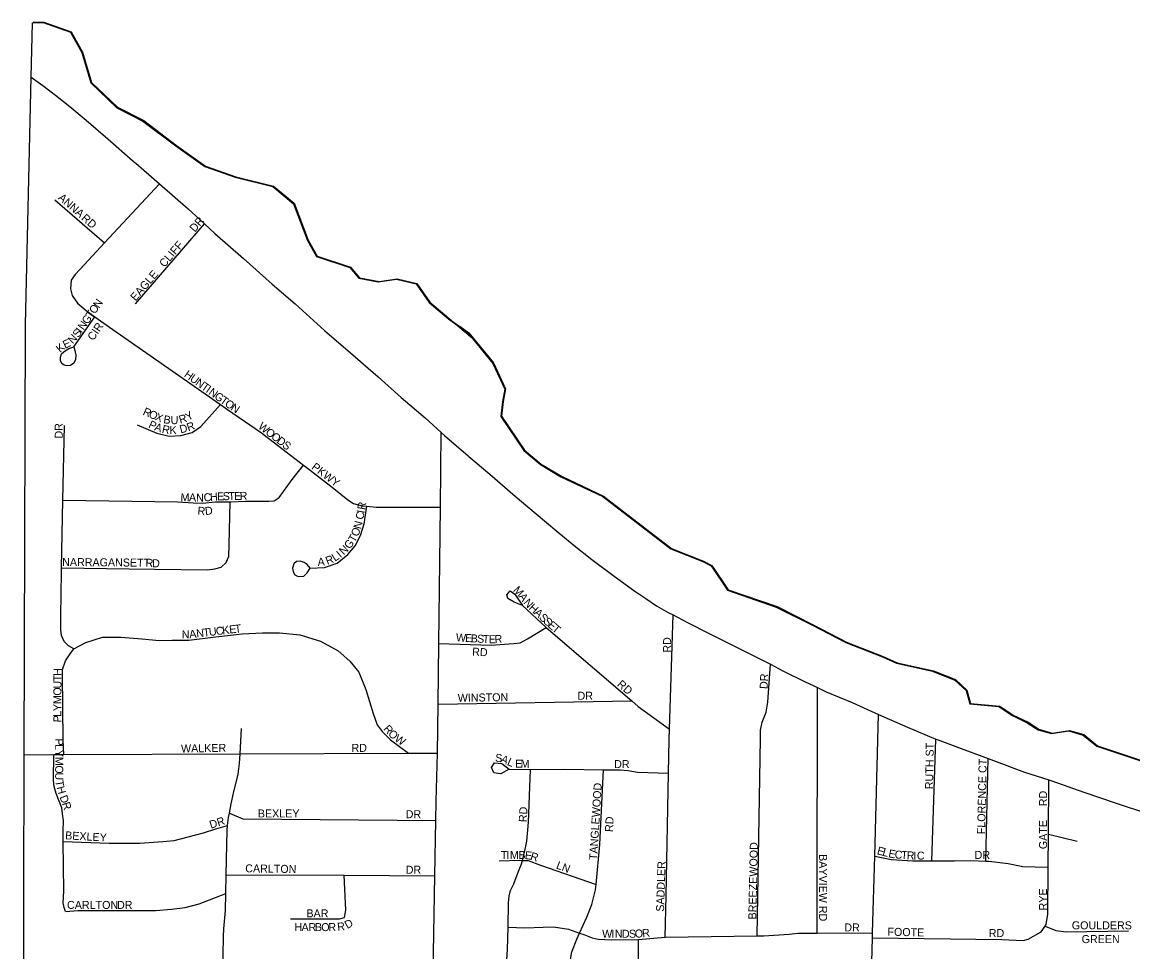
# Model space of a CAD drawing. Extents: x -561 to 1170, y 0 to 846.
# Drawn here: x 38.1 to 56.84, y 277.44 to 293.13 of the extents above; entities that cross this region are included whole.
import ezdxf

# ---------------------------------------------------------------- set-up
doc = ezdxf.new("R2010")
doc.units = 0
for name, color, linetype in [('GM_X_City_Street', 7, 'Continuous'), ('GM_X_City_Street_Text', 7, 'Continuous'), ('GM_X_County', 7, 'Continuous'), ('GM_X_Major_Lake', 7, 'Continuous'), ('GM_X_Major_River', 7, 'Continuous'), ('GM_X_US_Route', 7, 'Continuous')]:
    doc.layers.add(name, color=color, linetype=linetype)

msp = doc.modelspace()

# ---------------------------------------------------------------- linework, layer by layer
at = {"layer": 'GM_X_City_Street'}
for points in [[(40.416, 290.402), (39.489, 289.406), (39.15, 289.041), (38.994, 288.867), (38.929, 288.775), (38.913, 288.629), (38.946, 288.515), (39.033, 288.385), (39.18, 288.261), (39.328, 288.157), (39.63, 287.944), (41.446, 286.674), (41.562, 286.593), (42.138, 286.2), (42.556, 285.876), (42.849, 285.652), (42.958, 285.569), (43.359, 285.257), (43.593, 285.068), (43.69, 285.009), (43.837, 284.967), (43.914, 284.96), (44.07, 284.946), (44.441, 284.946), (44.441, 284.946)], [(38.653, 290.128), (39.489, 289.406)], [(40.013, 288.373), (41.174, 289.726)], [(38.971, 287.648), (38.99, 287.586), (39.005, 287.511), (39, 287.433), (38.971, 287.372), (38.918, 287.337), (38.853, 287.328), (38.808, 287.34), (38.767, 287.366), (38.745, 287.419), (38.744, 287.474), (38.762, 287.53), (38.809, 287.572), (38.885, 287.622), (38.971, 287.648), (39.328, 288.157)], [(40.042, 286.331), (40.373, 286.192), (40.579, 286.144), (40.779, 286.156), (40.969, 286.205), (41.114, 286.303), (41.446, 286.674)], [(38.753, 283.185), (38.753, 283.191), (38.755, 283.406), (38.765, 283.921), (38.788, 285.064), (38.814, 286.32)], [(44.832, 266.279), (44.833, 266.436), (44.841, 266.766), (44.894, 269.05), (44.906, 269.574), (44.922, 270.523), (44.94, 271.551), (44.973, 273.529), (45.065, 278.726), (45.081, 279.658), (45.087, 279.984), (45.108, 280.796), (45.117, 281.619), (45.129, 282.643), (45.156, 284.945), (45.17, 286.202)], [(41.977, 285.045), (41.981, 285.045), (42.11, 285.046), (42.261, 285.046), (42.353, 285.052), (42.434, 285.107), (42.655, 285.411), (42.849, 285.652)], [(38.788, 285.064), (40.724, 285.034), (40.984, 285.019), (41.146, 285.014), (41.357, 285.037), (41.607, 285.033), (41.628, 285.033), (41.866, 285.045), (41.977, 285.045)], [(40.332, 283.9), (41.226, 283.888), (41.351, 283.905), (41.459, 283.932), (41.54, 284.009), (41.588, 284.112), (41.593, 284.312), (41.607, 285.033)], [(42.958, 283.917), (42.908, 283.975), (42.855, 284.014), (42.788, 284.034), (42.731, 284.027), (42.683, 283.988), (42.661, 283.916), (42.672, 283.854), (42.702, 283.804), (42.755, 283.776), (42.85, 283.781), (42.91, 283.835), (42.958, 283.917), (43.202, 283.929), (43.413, 284.001), (43.596, 284.148), (43.72, 284.294), (43.806, 284.468), (43.87, 284.663), (43.914, 284.96)], [(44.441, 284.946), (45.156, 284.945)], [(38.765, 283.921), (39.903, 283.905), (39.904, 283.905)], [(39.904, 283.905), (40.33, 283.9), (40.332, 283.9)], [(46.541, 283.286), (46.401, 283.341), (46.293, 283.406), (46.277, 283.466), (46.332, 283.536), (46.413, 283.476), (46.541, 283.286), (46.939, 282.916), (48.387, 281.677), (48.496, 281.584), (49.023, 281.202)], [(38.803, 280.771), (38.791, 281.017), (38.781, 282.117), (38.781, 282.209), (38.829, 282.355), (38.91, 282.469), (38.974, 282.556), (38.882, 282.605), (38.811, 282.68), (38.762, 282.777), (38.751, 282.875), (38.753, 283.185)], [(48.963, 278.387), (48.963, 278.387), (49.006, 280.456), (49.018, 281.024), (49.023, 281.202), (49.082, 283.126)], [(38.974, 282.556), (39.174, 282.66), (39.455, 282.753), (39.769, 282.749), (40.121, 282.724), (40.419, 282.698), (40.63, 282.699), (40.912, 282.7), (41.366, 282.756), (41.81, 282.807), (42.153, 282.823), (42.443, 282.826), (42.784, 282.79), (43.131, 282.683), (43.429, 282.522), (43.63, 282.344), (43.782, 282.16), (43.897, 281.868), (44.023, 281.463), (44.089, 281.273), (44.176, 281.16), (44.312, 281.02), (44.616, 280.794)], [(45.129, 282.643), (46.014, 282.617), (46.236, 282.632), (46.398, 282.643), (46.501, 282.658), (46.625, 282.723), (46.939, 282.916)], [(50.5, 277.714), (50.558, 281.034), (50.559, 281.18), (50.586, 281.315), (50.652, 281.488), (50.68, 281.656), (50.724, 282.295)], [(51.516, 278.185), (51.518, 281.901)], [(45.117, 281.619), (48.387, 281.677)], [(52.182, 266.15), (52.18, 266.4), (52.256, 269.459), (52.259, 269.546), (52.259, 269.555), (52.28, 270.669), (52.296, 271.478), (52.337, 273.526), (52.366, 274.649), (52.392, 275.624), (52.447, 277.681), (52.449, 277.762), (52.484, 279.056), (52.547, 281.447)], [(41.778, 280.782), (41.778, 280.782), (41.8, 281.209)], [(53.446, 278.976), (53.517, 281.033)], [(38.136, 280.768), (38.635, 280.77), (38.803, 280.771), (41.778, 280.782), (44.616, 280.794), (45.108, 280.796)], [(38.829, 278.124), (38.807, 278.189), (38.79, 278.271), (38.801, 278.466), (38.793, 279.305), (38.791, 279.479), (38.796, 279.657), (38.779, 279.771), (38.768, 279.874), (38.724, 279.987), (38.675, 280.112), (38.642, 280.231), (38.626, 280.339), (38.635, 280.77)], [(41.485, 277.074), (41.499, 277.703), (41.504, 277.833), (41.53, 278.142), (41.536, 278.429), (41.542, 278.744), (41.553, 279.247), (41.557, 279.491), (41.567, 279.576), (41.583, 279.708), (41.597, 279.783), (41.626, 279.941), (41.668, 280.12), (41.743, 280.44), (41.769, 280.618), (41.778, 280.782)], [(54.359, 278.974), (54.401, 280.705)], [(46.318, 280.526), (46.175, 280.446), (46.056, 280.465), (46.021, 280.553), (46.07, 280.63), (46.192, 280.621), (46.318, 280.526), (46.675, 280.52), (47.253, 280.523), (47.907, 280.515), (47.983, 280.514), (48.188, 280.513), (48.323, 280.502), (48.48, 280.474), (49.006, 280.456)], [(46.236, 275.563), (46.226, 275.639), (46.236, 276.808), (46.237, 276.981), (46.276, 277.311), (46.288, 277.484), (46.297, 277.858), (46.308, 278.269), (46.314, 278.383), (46.341, 278.48), (46.396, 278.588), (46.467, 278.788), (46.521, 278.913), (46.541, 278.986), (46.576, 279.118), (46.615, 279.313), (46.644, 279.632), (46.675, 280.52)], [(47.346, 277.28), (47.374, 277.442), (47.456, 277.658), (47.503, 277.76), (47.625, 278.026), (47.713, 278.242), (47.774, 278.491), (47.782, 278.577), (47.847, 279.253), (47.907, 280.515)], [(54.991, 277.633), (55.072, 277.659), (55.295, 277.783), (55.359, 277.876), (55.376, 277.902), (55.404, 278.08), (55.41, 278.87), (55.414, 279.428), (55.421, 280.343)], [(41.597, 279.783), (41.822, 279.687), (45.081, 279.658)], [(38.793, 279.305), (39.566, 279.276), (40.086, 279.278), (40.475, 279.307), (40.665, 279.324), (40.903, 279.385), (41.162, 279.451), (41.368, 279.517), (41.567, 279.576)], [(55.414, 279.428), (55.902, 279.312)], [(52.484, 279.056), (52.77, 279), (53.127, 278.977), (53.446, 278.976), (53.522, 278.976), (53.83, 278.98), (54.106, 278.984), (54.359, 278.974), (54.408, 278.972), (54.738, 278.933), (54.957, 278.886)], [(46.149, 278.979), (46.489, 278.988), (46.541, 278.986), (46.635, 278.982), (46.846, 278.906), (47.782, 278.577)], [(54.957, 278.886), (54.97, 278.883), (55.41, 278.87)], [(41.542, 278.744), (43.53, 278.734), (45.065, 278.726)], [(42.629, 278), (43.327, 277.998), (43.452, 277.999), (43.538, 278.021), (43.56, 278.145), (43.53, 278.734)], [(38.829, 278.124), (39.045, 278.142), (39.197, 278.142), (40.063, 278.141), (40.355, 278.142), (40.62, 278.165), (40.848, 278.193), (41.086, 278.254), (41.361, 278.358), (41.536, 278.429)], [(48.948, 277.69), (48.963, 278.387)], [(51.516, 277.757), (51.516, 278.185), (51.516, 278.185)], [(46.297, 277.858), (46.581, 277.851), (46.89, 277.861), (47.063, 277.865), (47.317, 277.827), (47.503, 277.76), (47.576, 277.733), (47.716, 277.679), (47.818, 277.657), (48.045, 277.645), (48.5, 277.654), (48.948, 277.69), (50.5, 277.714), (50.613, 277.716), (51.04, 277.741), (51.186, 277.757), (51.354, 277.756), (51.516, 277.757), (52.449, 277.762)], [(55.359, 277.876), (55.543, 277.803), (55.716, 277.781), (56.765, 277.798)], [(48.479, 275.624), (48.494, 276.674), (48.495, 276.755), (48.5, 277.654)], [(52.447, 277.681), (54.629, 277.65), (54.991, 277.633)]]:
    msp.add_lwpolyline(points, dxfattribs=at)
at = {"layer": 'GM_X_County'}
msp.add_lwpolyline([(38.1, 266.459), (38.136, 280.768), (38.154, 288.024), (38.254, 292.2), (38.276, 293.118), (38.454, 293.119), (38.916, 292.959), (39.107, 292.613), (39.257, 292.104), (39.698, 291.684), (40.138, 291.459), (40.693, 291.039), (41.183, 290.69), (41.693, 290.509), (42.328, 290.355), (42.677, 290.064), (42.913, 289.442), (43.066, 289.172), (43.631, 288.986), (43.778, 288.808), (44.109, 288.745), (44.418, 288.79), (44.749, 288.71), (44.967, 288.397), (45.294, 288.123), (45.623, 287.878), (46.043, 287.371), (46.245, 286.933), (46.203, 286.721), (46.177, 286.472), (46.564, 285.899), (46.847, 285.662), (47.189, 285.458), (47.895, 285.126), (49.043, 284.243), (49.585, 284.029), (49.727, 283.953), (49.999, 283.543), (50.824, 283.26), (51.432, 282.954), (51.997, 282.659), (52.616, 282.418), (52.85, 282.311), (53.462, 282.178), (53.837, 282.028), (54.027, 281.85), (54.088, 281.629), (54.581, 281.582), (54.81, 281.432), (55.059, 281.308), (55.244, 281.19), (55.467, 281.126), (55.759, 281.171), (56.003, 281.101), (56.231, 280.913), (58.06, 280.304)], dxfattribs=at)
at = {"layer": 'GM_X_Major_Lake'}
for points in [[(38.287, 293.125), (38.466, 293.126), (38.927, 292.966), (39.119, 292.62), (39.268, 292.111), (39.709, 291.691), (40.15, 291.466), (40.705, 291.046), (41.194, 290.697), (41.705, 290.515), (42.34, 290.362), (42.688, 290.071), (42.925, 289.449), (43.078, 289.179), (43.642, 288.993), (43.79, 288.815), (44.121, 288.752), (44.429, 288.797), (44.76, 288.717), (44.979, 288.404), (45.305, 288.13)], [(38.287, 293.125), (38.466, 293.126), (38.927, 292.966), (39.119, 292.62), (39.268, 292.111), (39.709, 291.691), (40.15, 291.466), (40.705, 291.046), (41.194, 290.697), (41.705, 290.515), (42.34, 290.362), (42.688, 290.071), (42.925, 289.449), (43.078, 289.179), (43.642, 288.993), (43.79, 288.815), (44.121, 288.752), (44.429, 288.797), (44.76, 288.717), (44.979, 288.404), (45.738, 287.76)], [(45.355, 288.08), (45.635, 287.885), (46.054, 287.377), (46.257, 286.94), (46.214, 286.728), (46.188, 286.479), (46.576, 285.906), (46.858, 285.669), (47.201, 285.465), (47.907, 285.133), (49.054, 284.25), (49.597, 284.035), (49.738, 283.96), (50.011, 283.55), (50.836, 283.267), (51.444, 282.961), (52.009, 282.666), (52.628, 282.425), (52.861, 282.318), (53.474, 282.185), (53.848, 282.035), (54.039, 281.857), (54.099, 281.635), (54.593, 281.589), (54.821, 281.438), (55.071, 281.315), (55.256, 281.197), (55.478, 281.133), (55.77, 281.178), (56.014, 281.108), (56.243, 280.92), (58.072, 280.311)], [(45.738, 287.76), (46.054, 287.377), (46.257, 286.94), (46.214, 286.728), (46.188, 286.479), (46.576, 285.906), (46.858, 285.669), (47.201, 285.465), (47.907, 285.133), (49.054, 284.25), (49.597, 284.035), (49.738, 283.96), (50.011, 283.55), (50.836, 283.267), (51.444, 282.961), (52.009, 282.666), (52.628, 282.425), (52.861, 282.318), (53.474, 282.185), (53.848, 282.035), (54.039, 281.857), (54.099, 281.635), (54.593, 281.589), (54.821, 281.438), (55.071, 281.315), (55.256, 281.197), (55.478, 281.133), (55.77, 281.178), (56.014, 281.108), (56.243, 280.92), (58.072, 280.311)]]:
    msp.add_lwpolyline(points, dxfattribs=at)
at = {"layer": 'GM_X_Major_River'}
msp.add_lwpolyline([(45.488, 287.994), (45.635, 287.885), (46.054, 287.377), (46.257, 286.94), (46.214, 286.728), (46.188, 286.479), (46.576, 285.906), (46.858, 285.669), (47.201, 285.465), (47.907, 285.133), (49.054, 284.25), (49.597, 284.035), (49.738, 283.96), (50.011, 283.55), (50.836, 283.267), (51.444, 282.961), (52.009, 282.666), (52.628, 282.425), (52.861, 282.318), (53.474, 282.185), (53.848, 282.035), (54.039, 281.857), (54.099, 281.635), (54.593, 281.589), (54.821, 281.438), (55.071, 281.315), (55.256, 281.197), (55.478, 281.133), (55.77, 281.178), (56.014, 281.108), (56.243, 280.92), (58.072, 280.311)], dxfattribs=at)
at = {"layer": 'GM_X_US_Route'}
for points in [[(38.254, 292.2), (38.448, 292.058), (38.664, 291.895), (38.902, 291.706), (39.178, 291.473), (39.546, 291.159), (39.968, 290.786), (39.978, 290.777), (40.015, 290.746)], [(40.015, 290.746), (40.373, 290.439), (40.416, 290.402), (40.898, 289.979), (41.174, 289.726), (41.352, 289.562), (41.834, 289.14), (42.32, 288.707), (42.704, 288.377), (43.202, 287.927), (43.64, 287.549), (44.105, 287.143), (44.494, 286.796), (44.9, 286.45), (45.17, 286.202), (45.224, 286.152), (45.625, 285.809), (45.635, 285.8), (45.992, 285.502), (46.42, 285.129), (46.771, 284.831), (47.123, 284.539), (47.415, 284.3), (47.712, 284.062), (48.091, 283.781), (48.437, 283.526), (48.621, 283.402), (48.805, 283.283), (48.999, 283.169), (49.082, 283.126), (49.313, 283.007), (49.702, 282.806), (50.151, 282.584), (50.524, 282.4), (50.724, 282.295), (50.935, 282.184), (51.309, 281.999), (51.518, 281.901), (51.666, 281.832), (52.104, 281.648), (52.547, 281.447), (53.039, 281.231), (53.517, 281.033), (53.537, 281.025), (53.986, 280.857), (54.401, 280.705), (54.489, 280.673), (55.013, 280.472), (55.421, 280.343), (55.473, 280.326), (56.014, 280.137), (56.576, 279.947), (57.085, 279.779)]]:
    msp.add_lwpolyline(points, dxfattribs=at)

# ---------------------------------------------------------------- texts
at = {"layer": 'GM_X_City_Street_Text'}
for s, rotation, p in [('ANNA', 319.0834, (38.695, 290.148)), ('RD', 319.0917, (39.087, 289.803)), ('DR', 49.4006, (41.012, 289.575)), ('CLIFF', 49.2672, (40.501, 288.981)), ('EAGLE', 49.3979, (40.014, 288.411)), ('N', 55.0671, (39.395, 288.291)), ('T', 55.0707, (39.272, 288.115)), ('O', 55.0671, (39.327, 288.193)), ('N', 55.0671, (39.136, 287.921)), ('G', 55.0671, (39.204, 288.018)), ('CIR', 55.624, (39.301, 287.743)), ('N', 47.5181, (38.956, 287.69)), ('S', 55.6483, (39.049, 287.794)), ('I', 55.0796, (39.102, 287.872)), ('K', 40.5373, (38.742, 287.543)), ('E', 25.3247, (38.824, 287.615)), ('H', 324.2972, (40.82, 287.156)), ('U', 324.3171, (40.917, 287.087)), ('N', 324.2972, (41.013, 287.017)), ('T', 324.3238, (41.11, 286.948)), ('I', 324.2972, (41.187, 286.892)), ('N', 324.2972, (41.235, 286.858)), ('G', 324.3171, (41.331, 286.788)), ('T', 324.294, (41.428, 286.719)), ('O', 324.9088, (41.506, 286.663)), ('N', 326.1408, (41.606, 286.593)), ('R', 336.972, (40.125, 286.508)), ('O', 336.9607, (40.223, 286.466)), ('X', 336.9782, (40.332, 286.42)), ('Y', 30.5185, (40.901, 286.397)), ('DR', 90, (38.784, 286.102)), ('P', 334.1314, (40.218, 286.293)), ('A', 341.5715, (40.321, 286.244)), ('R', 348.1453, (40.45, 286.202)), ('B', 351.3981, (40.477, 286.363)), ('U', 0.0208, (40.605, 286.345)), ('R', 16.9049, (40.767, 286.352)), ('D', 13.7337, (40.774, 286.189)), ('R', 19.5905, (40.904, 286.222)), ('W', 320.471, (42.07, 286.287)), ('K', 0.522, (40.587, 286.177)), ('O', 322.6419, (42.193, 286.185)), ('O', 322.6995, (42.288, 286.113)), ('D', 322.6886, (42.382, 286.041)), ('S', 322.7094, (42.477, 285.969)), ('PKWY', 322.8566, (42.971, 285.599)), ('S', 1.175, (41.485, 285.061)), ('T', 1.2062, (41.581, 285.063)), ('E', 1.175, (41.676, 285.065)), ('R', 1.1992, (41.771, 285.067)), ('M', 358.5975, (40.771, 285.046)), ('A', 358.6022, (40.913, 285.042)), ('N', 359.0919, (41.033, 285.04)), ('C', 5.5065, (41.168, 285.038)), ('H', 4.4415, (41.274, 285.049)), ('E', 1.8582, (41.391, 285.058)), ('R', 79.9906, (43.885, 284.892)), ('R', 354.6736, (41.054, 284.82)), ('D', 7.3231, (41.192, 284.81)), ('C', 79.4355, (43.854, 284.727)), ('I', 80.0069, (43.874, 284.834)), ('N', 74.9281, (43.814, 284.566)), ('T', 60.4985, (43.71, 284.339)), ('O', 68.2674, (43.765, 284.439)), ('N', 43.9004, (43.525, 284.129)), ('G', 51.8606, (43.624, 284.227)), ('NARRAGANSETT', 359.4887, (38.774, 283.953)), ('R', 356.0139, (40.178, 283.941)), ('A', 4.3752, (43.089, 283.953)), ('R', 20.5853, (43.248, 283.971)), ('L', 32.6255, (43.376, 284.023)), ('I', 38.9441, (43.469, 284.083)), ('D', 358.0681, (40.29, 283.933)), ('M', 312.8875, (46.375, 283.536)), ('A', 306.5552, (46.47, 283.435)), ('N', 312.1649, (46.55, 283.328)), ('H', 316.8478, (46.638, 283.232)), ('A', 316.8237, (46.725, 283.151)), ('S', 316.8299, (46.811, 283.069)), ('E', 6.8184, (41.6, 282.812)), ('T', 6.8184, (41.694, 282.823)), ('S', 317.4769, (46.882, 283.003)), ('E', 319.8579, (46.957, 282.935)), ('T', 320.495, (47.03, 282.872)), ('N', 1.2458, (40.794, 282.729)), ('A', 5.9479, (40.925, 282.733)), ('N', 6.8234, (41.045, 282.745)), ('T', 6.8345, (41.163, 282.759)), ('U', 6.841, (41.258, 282.771)), ('C', 6.8162, (41.376, 282.785)), ('K', 6.841, (41.482, 282.798)), ('W', 356.6187, (45.416, 282.682)), ('E', 356.6103, (45.57, 282.673)), ('B', 356.5979, (45.665, 282.667)), ('S', 356.634, (45.772, 282.661)), ('T', 356.6836, (45.867, 282.655)), ('E', 0.4036, (45.971, 282.649)), ('R', 3.2533, (46.074, 282.65)), ('RD', 356.9887, (45.689, 282.441)), ('RD', 90, (49.048, 282.49)), ('H', 88.3275, (38.762, 282.097)), ('T', 89.8324, (38.762, 282.003)), ('RD', 319.3961, (48.128, 281.939)), ('DR', 86.9884, (50.676, 281.874)), ('O', 89.836, (38.761, 281.765)), ('U', 89.8295, (38.762, 281.884)), ('DR', 0, (47.47, 281.696)), ('M', 89.8423, (38.761, 281.623)), ('WINSTON', 0.8947, (45.45, 281.66)), ('L', 89.8324, (38.76, 281.409)), ('Y', 89.8295, (38.761, 281.504)), ('P', 89.8361, (38.76, 281.314)), ('R', 310.9438, (44.187, 281.2)), ('O', 315.0947, (44.264, 281.111)), ('W', 326.8027, (44.371, 281.008)), ('P', 270.082, (38.657, 281.041)), ('L', 270.0683, (38.657, 280.946)), ('WALKER', 0.9705, (40.781, 280.805)), ('RD', 0, (43.656, 280.817)), ('RUTH ST', 88.9954, (53.468, 280.186)), ('Y', 270.0771, (38.657, 280.851)), ('M', 270.0729, (38.657, 280.732)), ('S', 356.1178, (46.077, 280.65)), ('A', 336.4814, (46.16, 280.647)), ('L', 337.8104, (46.272, 280.598)), ('O', 270.0765, (38.657, 280.589)), ('E', 359.3679, (46.415, 280.551)), ('M', 358.5608, (46.509, 280.55)), ('DR', 0, (48.088, 280.543)), ('FLORENCE CT', 88.7675, (54.347, 279.426)), ('U', 270.2237, (38.657, 280.47)), ('T', 278.6145, (38.659, 280.33)), ('H', 285.9065, (38.678, 280.217)), ('TANGLEWOOD', 86.5319, (47.801, 278.989)), ('RD', 90, (55.392, 279.9)), ('D', 291.7448, (38.727, 280.055)), ('R', 288.1162, (38.77, 279.947)), ('BEXLEY', 0, (42.076, 279.71)), ('DR', 0, (44.571, 279.698)), ('RD', 87.1392, (46.613, 279.628)), ('DR', 17.5278, (41.284, 279.519)), ('RD', 86.9833, (48.066, 279.462)), ('GATE', 90, (55.392, 279.176)), ('BEXLEY', 356.8756, (38.822, 279.342)), ('BREEZEWOOD', 88.806, (50.486, 277.988)), ('E', 344.9366, (52.514, 279.093)), ('T', 359.8634, (46.175, 279.01)), ('I', 359.8251, (46.27, 279.01)), ('M', 359.8498, (46.329, 279.01)), ('B', 359.8543, (46.472, 279.01)), ('E', 353.429, (46.575, 279.01)), ('R', 343.324, (46.663, 279)), ('BAYVIEW RD', 270, (51.546, 279.092)), ('L', 344.9102, (52.605, 279.069)), ('E', 348.8292, (52.707, 279.042)), ('C', 355.5863, (52.817, 279.021)), ('T', 356.2729, (52.926, 279.012)), ('R', 356.9149, (53.022, 279.006)), ('I', 359.0948, (53.135, 279)), ('C', 359.9228, (53.196, 278.999)), ('DR', 0, (54.17, 279.011)), ('CARLTON', 359.1324, (41.863, 278.785)), ('DR', 0, (44.571, 278.761)), ('LN', 338.7492, (47.099, 278.854)), ('SADDLER', 88.211, (48.929, 278.119)), ('RYE', 90, (55.392, 278.142)), ('CARLTON', 0, (38.857, 278.167)), ('DR', 0, (39.7, 278.167)), ('BAR', 0, (42.896, 278.025)), ('H', 0, (42.694, 277.793)), ('A', 0, (42.813, 277.793)), ('R', 0, (42.932, 277.793)), ('B', 0, (43.039, 277.793)), ('O', 0.0549, (43.146, 277.793)), ('R', 1.1042, (43.267, 277.793)), ('R', 6.0182, (43.422, 277.797)), ('D', 29.8156, (43.586, 277.827)), ('DR', 0, (51.972, 277.787)), ('GOULDERS', 0, (55.81, 277.823)), ('W', 0.0336, (47.886, 277.68)), ('I', 0.0399, (48.04, 277.68)), ('N', 0.0437, (48.099, 277.681)), ('D', 0.0219, (48.218, 277.681)), ('S', 0.0455, (48.337, 277.681)), ('O', 3.1454, (48.44, 277.681)), ('R', 6.6502, (48.568, 277.688)), ('FOOTE', 358.7277, (52.698, 277.716)), ('RD', 0, (54.408, 277.692)), ('GREEN', 0, (55.976, 277.591))]:
    msp.add_text(s, height=0.135, rotation=rotation, dxfattribs=at).set_placement(p)

doc.saveas('drawing.dxf')
